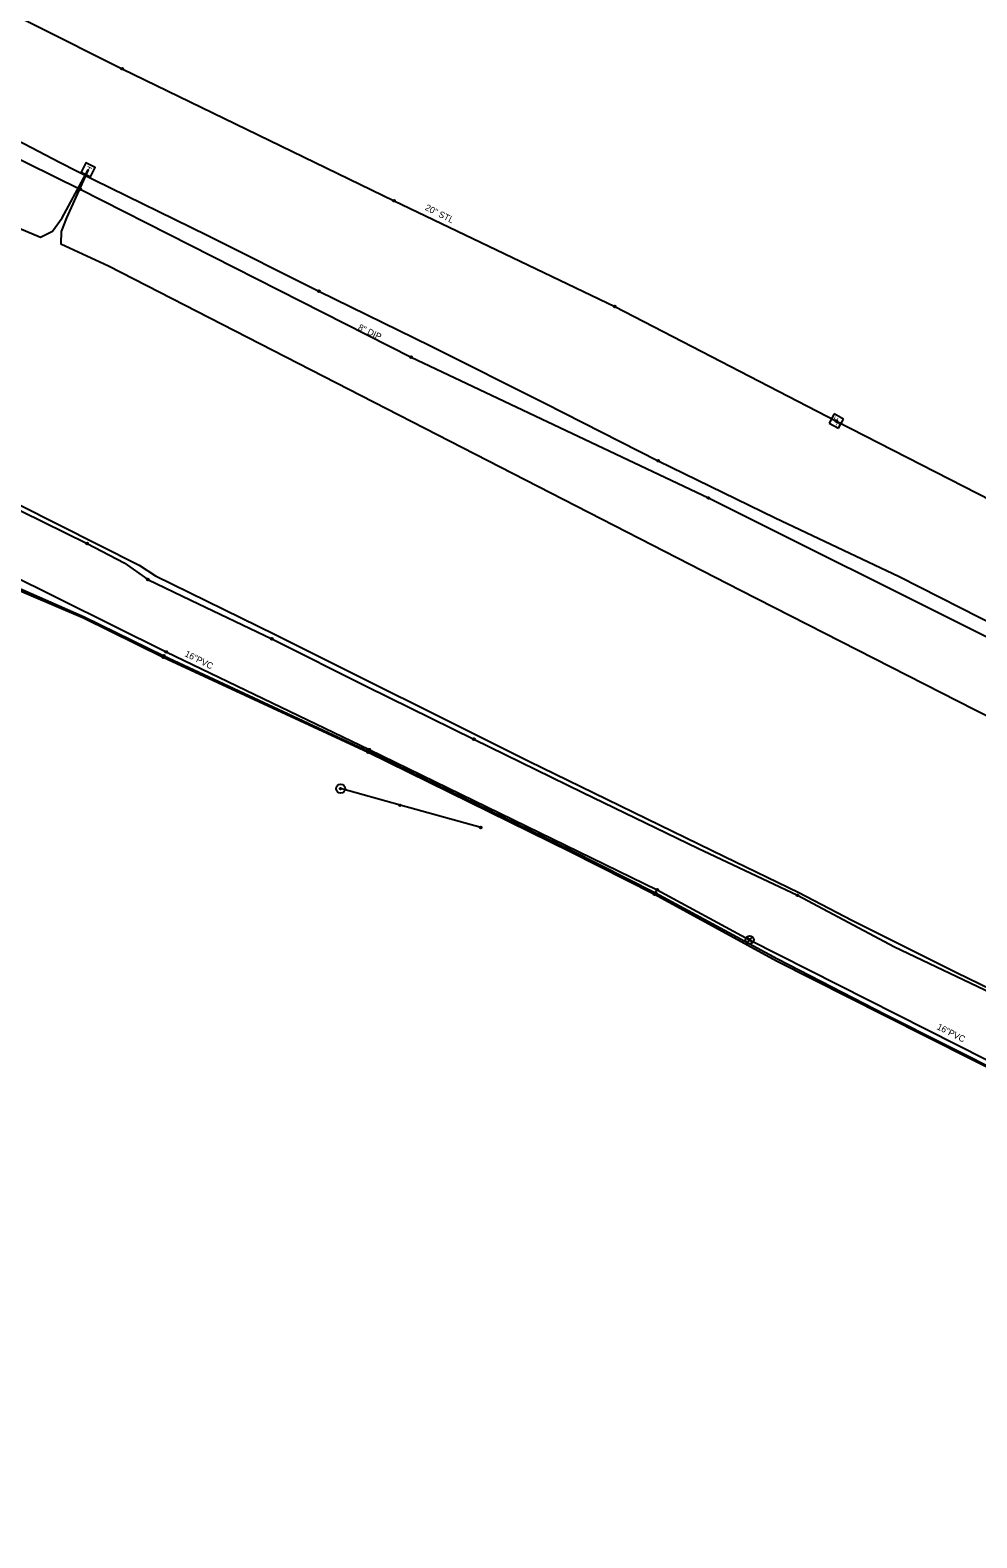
# Model space of a CAD drawing. Extents: x 2244485 to 2250986, y 199568 to 203007.
# Drawn here: x 2248849 to 2249364, y 200055 to 200876 of the extents above; entities that cross this region are included whole.
import ezdxf

# ---------------------------------------------------------------- set-up
doc = ezdxf.new("R2010")
doc.units = 0
for name, color, linetype in [('Default', 7, 'Continuous'), ('Exist Utilities Gas Meter CELL', 7, 'Continuous'), ('Exist Utilities Gas UG Line SUE LOS B', 7, 'Continuous'), ('Exist Utilities Gas UG Line SUE LOS B Text', 7, 'Continuous'), ('Exist Utilities Other Pole CELL', 7, 'Continuous'), ('Exist Utilities Power UG Cable SUE LOS B', 7, 'Continuous'), ('Exist Utilities Sanitary Sewer Forced Main SUE LOS B', 7, 'Continuous'), ('Exist Utilities Sanitary Sewer Forced Main SUE LOS B Text', 7, 'Continuous'), ('Exist Utilities Telephone Pedestal CELL', 7, 'Continuous'), ('Exist Utilities Telephone UG Cable SUE LOS C', 7, 'Continuous'), ('Exist Utilities Telephone UG FO SUE LOS B', 7, 'Continuous'), ('Exist Utilities Telephone UG FO SUE LOS C', 7, 'Continuous'), ('Exist Utilities Water UG Line SUE LOS B', 7, 'Continuous'), ('Exist Utilities Water UG Line SUE LOS B Text', 7, 'Continuous'), ('Exist Utilities Water Valve CELL', 7, 'Continuous')]:
    doc.layers.add(name, color=color, linetype=linetype)

# ---------------------------------------------------------------- blocks, each defined once
blk = doc.blocks.new('SurveyPointCell')
at = {"layer": 'Default'}
for p, q in [((-0.5, 0), (0.5, 0)), ((0, -0.5), (0, 0.5))]:
    blk.add_line(p, q, dxfattribs=at)
blk.add_circle((0, 0), 0.5, dxfattribs=at)

msp = doc.modelspace()

# ---------------------------------------------------------------- linework, layer by layer
at = {"layer": 'Exist Utilities Gas Meter CELL'}
for p, q in [((2249286.25, 200666.97), (2249283.48, 200661.96)), ((2249283.48, 200661.96), (2249288.49, 200659.19)), ((2249291.26, 200664.2), (2249286.25, 200666.97)), ((2249287.37, 200663.08), (2249287.37, 200663.08)), ((2249288.49, 200659.19), (2249291.26, 200664.2))]:
    msp.add_line(p, q, dxfattribs=at)
at = {"layer": 'Exist Utilities Gas UG Line SUE LOS B'}
msp.add_lwpolyline([(2247602.4, 201501.88), (2247749.1, 201426.01), (2247995.53, 201302.57), (2248159.78, 201224.66), (2248327.53, 201140.85), (2248373.07, 201115.64), (2248475.56, 201067.34), (2248547.65, 201031.24), (2248651.39, 200979.65), (2248754.41, 200927.49), (2248898.77, 200854.93), (2249046.68, 200783.06), (2249166.77, 200725.47), (2249287.36, 200663.03), (2249402.68, 200604.16)], dxfattribs=at)
at = {"layer": 'Exist Utilities Other Pole CELL'}
msp.add_circle((2249017.59, 200462.97), 2.46, dxfattribs=at)
at = {"layer": 'Exist Utilities Power UG Cable SUE LOS B'}
msp.add_lwpolyline([(2249093.85, 200441.82), (2249049.93, 200453.92), (2249017.62, 200462.99)], dxfattribs=at)
at = {"layer": 'Exist Utilities Sanitary Sewer Forced Main SUE LOS B'}
msp.add_lwpolyline([(2247735.41, 201350.67), (2247801.59, 201317.51), (2247922.39, 201259.82), (2248074.17, 201183.48), (2248161.38, 201141.9), (2248228.53, 201112.29), (2248334.87, 201058.12), (2248487.25, 200983.06), (2248649.22, 200895.6), (2248733.43, 200859.57), (2248875.85, 200789.39), (2249055.92, 200697.85), (2249217.76, 200621.23), (2249370.62, 200544.89)], dxfattribs=at)
at = {"layer": 'Exist Utilities Telephone Pedestal CELL'}
msp.add_line((2248880.19, 200799.94), (2248880.19, 200799.94), dxfattribs=at)
msp.add_lwpolyline([(2248876.51, 200798.59), (2248881.54, 200796.15), (2248883.98, 200801.18), (2248878.95, 200803.62), (2248876.51, 200798.59)], dxfattribs=at)
at = {"layer": 'Exist Utilities Telephone UG Cable SUE LOS C'}
msp.add_lwpolyline([(2248238.7, 201066.28), (2248423.59, 200974.24), (2248773.82, 200799.99), (2248835.88, 200770.97), (2248854.39, 200763.25), (2248860.78, 200766.45), (2248866.15, 200773.75), (2248880.19, 200799.94), (2248868.48, 200773.69), (2248865.46, 200766.31), (2248865.37, 200759.63), (2248891.36, 200747.54), (2249235.17, 200571.04), (2249362.52, 200506.1), (2249646.99, 200363.79)], dxfattribs=at)
at = {"layer": 'Exist Utilities Telephone UG FO SUE LOS B'}
for points in [[(2247734.6, 201364.13), (2247798.15, 201331.66), (2247859.88, 201301.14), (2247925.6, 201269.67), (2247988.72, 201238.28), (2248114.06, 201176.6), (2248183.16, 201141.53), (2248221.91, 201121.81), (2248290.07, 201088.12), (2248488.94, 200988.89), (2248609.32, 200928.77), (2248687.7, 200891.02), (2248748.44, 200861.37), (2248829.89, 200822.11), (2248864.68, 200804.04), (2248883.46, 200794.42), (2248944.92, 200764.27), (2249005.82, 200733.82), (2249066.5, 200704.1), (2249128.64, 200672.91), (2249190.46, 200641.51), (2249254.14, 200610.49), (2249321.49, 200578.44), (2249387.5, 200544.86)], [(2248344.53, 200859.83), (2248419.29, 200821.92), (2248466.62, 200800.01), (2248552.5, 200756.23), (2248616.5, 200725.07), (2248683.2, 200691.48), (2248772.25, 200649.25), (2248879.65, 200596.48), (2248899.78, 200585.98), (2248912.71, 200576.87), (2248936.09, 200565.52), (2248980.22, 200544.6), (2249032.26, 200518.49), (2249090.09, 200489.91), (2249149.46, 200460.97), (2249211.92, 200430.6), (2249266.25, 200404.93), (2249319.08, 200376.82), (2249375.45, 200350.06)], [(2248834.42, 200574.52), (2248877.75, 200555.98), (2248921.13, 200534.6), (2249032.64, 200482.8), (2249142.58, 200428.84), (2249188.38, 200405.49), (2249254.87, 200369.28), (2249313.69, 200339.47), (2249478.6, 200256.38)], [(2248834.42, 200574.52), (2248840.11, 200573.18), (2248878.1, 200556.55), (2248921.45, 200535.34), (2249032.65, 200483.49), (2249143.05, 200429.5), (2249188.93, 200406.33), (2249255.33, 200370.44), (2249314.07, 200340.07), (2249478.96, 200257.14)]]:
    msp.add_lwpolyline(points, dxfattribs=at)
at = {"layer": 'Exist Utilities Telephone UG FO SUE LOS C'}
msp.add_lwpolyline([(2248345.35, 200861.45), (2248395.63, 200836.07), (2248465.71, 200802.05), (2248553.74, 200758.66), (2248684.23, 200693.17), (2248820.3, 200628.68), (2248908.04, 200584.64), (2248916.96, 200578.87), (2248981.98, 200546.97), (2249120.09, 200477.99), (2249226.44, 200426.02), (2249266.92, 200406.38), (2249295.86, 200391.44), (2249352.73, 200362.96), (2249442.05, 200319.48)], dxfattribs=at)
at = {"layer": 'Exist Utilities Water UG Line SUE LOS B'}
msp.add_lwpolyline([(2248835.51, 200580.83), (2248922.65, 200537.42), (2249033.15, 200484.25), (2249189.81, 200407.98), (2249240.08, 200380.66), (2249481.52, 200258.57), (2249600.85, 200198.31), (2249670.02, 200162.8), (2249862.82, 200069.86), (2249895.12, 200055.15)], dxfattribs=at)
at = {"layer": 'Exist Utilities Water Valve CELL'}
msp.add_lwpolyline([(2249241.78, 200382.25), (2249238.63, 200379.1), (2249240.2, 200380.68), (2249241.78, 200379.1), (2249238.63, 200382.25)], dxfattribs=at)
msp.add_circle((2249240.2, 200380.68), 2.23, dxfattribs=at)

# ---------------------------------------------------------------- block references
at = {"layer": 'Default'}
for p in [(2248898.77, 200854.93), (2248875.85, 200789.39), (2249046.68, 200783.06), (2249005.82, 200733.82), (2249166.77, 200725.47), (2249055.92, 200697.85), (2249287.36, 200663.03), (2249190.46, 200641.51), (2249217.76, 200621.23), (2248879.65, 200596.48), (2248912.71, 200576.87), (2248980.22, 200544.6), (2248921.13, 200534.6), (2248921.45, 200535.34), (2248922.65, 200537.42), (2249090.09, 200489.91), (2249032.64, 200482.8), (2249032.65, 200483.49), (2249033.15, 200484.25), (2249017.62, 200462.99), (2249049.93, 200453.92), (2249093.85, 200441.82), (2249189.81, 200407.98), (2249188.38, 200405.49), (2249188.93, 200406.33), (2249266.25, 200404.93), (2249240.08, 200380.66)]:
    msp.add_blockref('SurveyPointCell', p, dxfattribs=at)

# ---------------------------------------------------------------- texts
at = {"layer": 'Exist Utilities Gas Meter CELL'}
for p in [(2249285.26, 200663.57), (2249286.8, 200661.04)]:
    msp.add_text('H', height=2.5, rotation=331.07712, dxfattribs=at).set_placement(p)
at = {"layer": 'Exist Utilities Gas UG Line SUE LOS B Text'}
msp.add_text('20" STL', height=3.5, rotation=333.09153, dxfattribs=at).set_placement((2249063.22, 200778.23))
at = {"layer": 'Exist Utilities Sanitary Sewer Forced Main SUE LOS B Text'}
msp.add_text('8" DIP', height=3.5, rotation=334.4319, dxfattribs=at).set_placement((2249026.74, 200712.93))
at = {"layer": 'Exist Utilities Telephone Pedestal CELL'}
msp.add_text('T', height=3.42, rotation=334.12094, dxfattribs=at).set_placement((2248878.43, 200798.89))
at = {"layer": 'Exist Utilities Water UG Line SUE LOS B Text'}
for p in [(2248932.45, 200535.31), (2249341.69, 200332.21)]:
    msp.add_text('16"PVC', height=3.5, rotation=333.09153, dxfattribs=at).set_placement(p)

doc.saveas('drawing.dxf')
